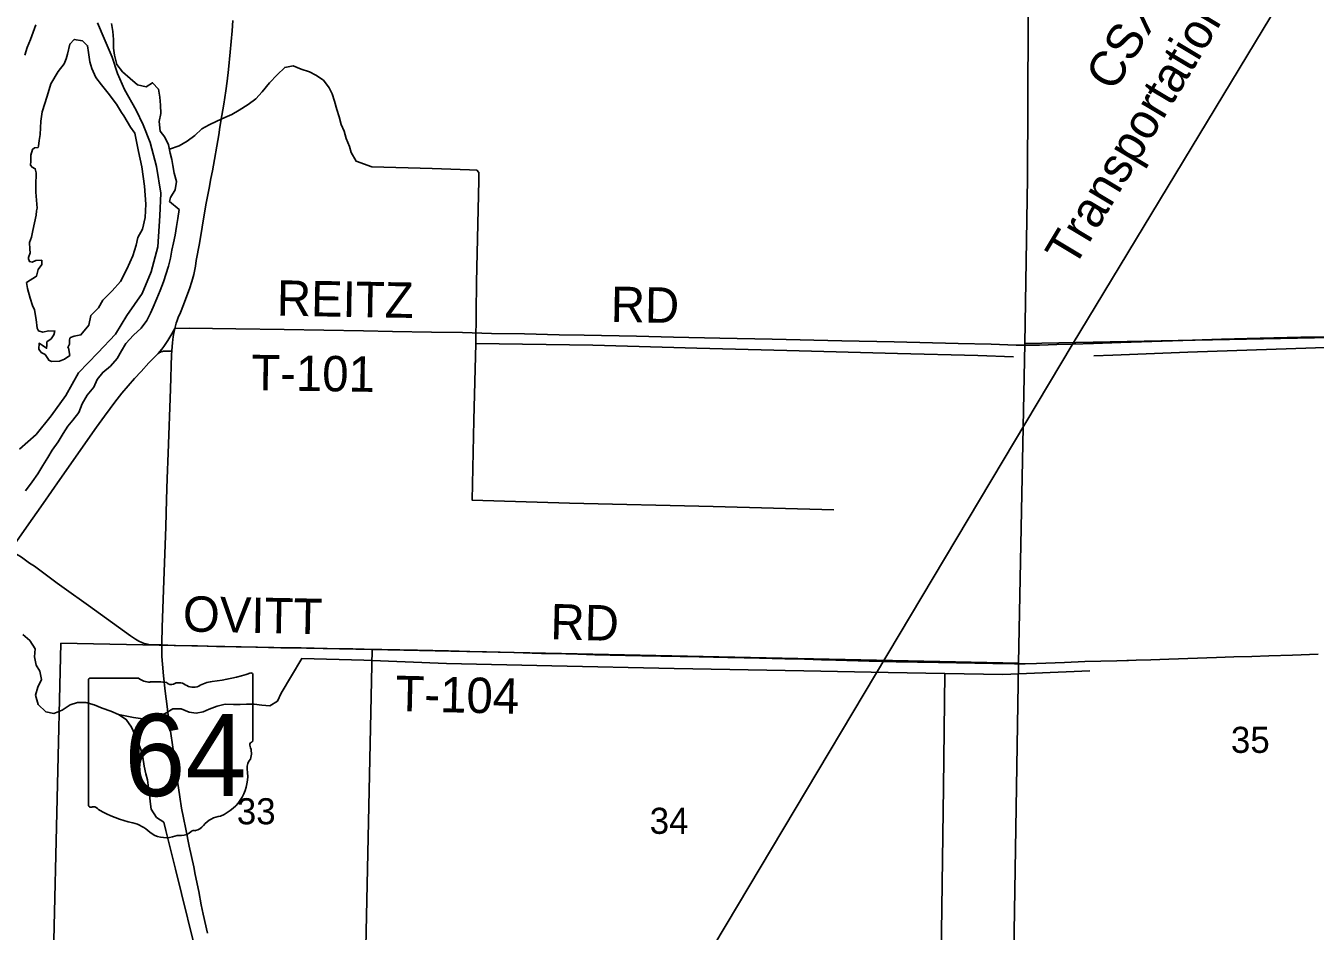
# Model space of a CAD drawing. Extents: x 1443599 to 1910620, y 1028088 to 1361369.
# Drawn here: x 1635252 to 1646176, y 1269443 to 1277115 of the extents above; entities that cross this region are included whole.
import ezdxf

# ---------------------------------------------------------------- set-up
doc = ezdxf.new("R2010")
doc.units = 0
for name, color, linetype in [('GM_X_Adjacent_County', 7, 'Continuous'), ('GM_X_Corporation', 7, 'Continuous'), ('GM_X_County', 7, 'Continuous'), ('GM_X_Interchange_Ramps', 7, 'Continuous'), ('GM_X_Major_River', 7, 'Continuous'), ('GM_X_Minor_River', 7, 'Continuous'), ('GM_X_Rail_Line', 7, 'Continuous'), ('GM_X_Rail_Line_Text', 7, 'Continuous'), ('GM_X_Section', 7, 'Continuous'), ('GM_X_Section_Text', 7, 'Continuous'), ('GM_X_State_Location', 7, 'Continuous'), ('GM_X_State_Route', 7, 'Continuous'), ('GM_X_State_Shield', 7, 'Continuous'), ('GM_X_Township', 7, 'Continuous'), ('GM_X_Township_Road', 7, 'Continuous'), ('GM_X_Township_Road_Text', 7, 'Continuous')]:
    doc.layers.add(name, color=color, linetype=linetype)

msp = doc.modelspace()

# ---------------------------------------------------------------- linework, layer by layer
at = {"layer": 'GM_X_Adjacent_County'}
msp.add_lwpolyline([(1635861, 1277141), (1635917, 1277006), (1635983, 1276848), (1636030, 1276711), (1636088, 1276575), (1636186, 1276399), (1636248, 1276276), (1636305, 1276126), (1636360, 1275922), (1636396, 1275697), (1636387, 1275504), (1636370, 1275242), (1636315, 1275030), (1636237, 1274848), (1636108, 1274660), (1636011, 1274501), (1635862, 1274343), (1635698, 1274173), (1635591, 1273982), (1635466, 1273811), (1635341, 1273653), (1635200, 1273527)], dxfattribs=at)
at = {"layer": 'GM_X_Corporation'}
msp.add_lwpolyline([(1635861, 1277141), (1635917, 1277006), (1635983, 1276848), (1636030, 1276711), (1636088, 1276575), (1636186, 1276399), (1636248, 1276276), (1636305, 1276126), (1636360, 1275922), (1636396, 1275697), (1636387, 1275504), (1636370, 1275242), (1636315, 1275030), (1636237, 1274848), (1636108, 1274660), (1636011, 1274501), (1635862, 1274343), (1635698, 1274173), (1635591, 1273982), (1635466, 1273811), (1635341, 1273653), (1635200, 1273527)], dxfattribs=at)
at = {"layer": 'GM_X_County'}
msp.add_lwpolyline([(1635200, 1273527), (1635341, 1273653), (1635466, 1273811), (1635591, 1273982), (1635698, 1274173), (1635862, 1274343), (1636011, 1274501), (1636108, 1274660), (1636237, 1274848), (1636315, 1275030), (1636370, 1275242), (1636387, 1275504), (1636396, 1275697), (1636360, 1275922), (1636305, 1276126), (1636248, 1276276), (1636186, 1276399), (1636088, 1276575), (1636030, 1276711), (1635983, 1276848), (1635917, 1277006), (1635861, 1277141)], dxfattribs=at)
at = {"layer": 'GM_X_Interchange_Ramps'}
msp.add_lwpolyline([(1636515, 1274551), (1636503, 1274529), (1636489, 1274505), (1636455, 1274448), (1636422, 1274398), (1636404, 1274375), (1636373, 1274339)], dxfattribs=at)
at = {"layer": 'GM_X_Major_River'}
msp.add_line((1636063, 1276379), (1636022, 1276451), dxfattribs=at)
for points in [[(1635337, 1277123), (1635292, 1276998), (1635265, 1276932), (1635243, 1276865)], [(1635250, 1273175), (1635306, 1273250), (1635353, 1273318), (1635396, 1273389), (1635440, 1273457), (1635477, 1273520), (1635526, 1273591), (1635570, 1273659), (1635609, 1273722), (1635650, 1273774), (1635701, 1273837), (1635731, 1273911), (1635772, 1273986), (1635828, 1274053), (1635857, 1274117), (1635904, 1274178), (1635969, 1274231), (1636025, 1274297), (1636064, 1274362), (1636101, 1274424), (1636165, 1274493), (1636230, 1274554), (1636277, 1274617), (1636308, 1274679), (1636331, 1274732), (1636363, 1274804), (1636392, 1274872), (1636419, 1274946), (1636462, 1275079), (1636478, 1275145), (1636489, 1275213), (1636504, 1275277), (1636517, 1275341), (1636529, 1275415), (1636540, 1275483), (1636551, 1275557), (1636469, 1275627), (1636479, 1275661), (1636517, 1275724), (1636528, 1275796), (1636509, 1275865), (1636498, 1275931), (1636489, 1275982), (1636476, 1276036), (1636460, 1276105), (1636429, 1276172), (1636390, 1276223), (1636383, 1276303), (1636397, 1276371), (1636394, 1276443), (1636389, 1276509), (1636377, 1276578), (1636326, 1276633), (1636271, 1276598), (1636199, 1276615), (1636136, 1276669), (1636071, 1276726), (1636024, 1276787), (1636003, 1276865), (1635995, 1276926), (1635994, 1276999), (1635991, 1277067), (1635979, 1277135)], [(1636022, 1276451), (1635950, 1276543), (1635894, 1276616), (1635845, 1276678), (1635813, 1276753), (1635796, 1276809), (1635784, 1276890), (1635776, 1276946), (1635733, 1276987), (1635663, 1276999), (1635624, 1276960), (1635606, 1276876), (1635595, 1276834), (1635578, 1276794), (1635526, 1276729), (1635465, 1276624), (1635433, 1276519), (1635392, 1276387), (1635380, 1276307), (1635373, 1276195), (1635366, 1276143), (1635359, 1276095), (1635356, 1276085), (1635326, 1276082), (1635310, 1276068), (1635295, 1276020), (1635295, 1275968), (1635293, 1275934), (1635306, 1275916), (1635332, 1275903), (1635341, 1275869), (1635337, 1275762), (1635337, 1275706), (1635350, 1275571), (1635343, 1275547), (1635339, 1275509), (1635313, 1275380), (1635300, 1275324), (1635283, 1275278), (1635286, 1275222), (1635289, 1275191), (1635276, 1275152), (1635274, 1275140), (1635283, 1275117), (1635307, 1275113), (1635337, 1275126), (1635387, 1275129), (1635387, 1275093), (1635358, 1275049), (1635342, 1274993), (1635259, 1274939), (1635266, 1274889), (1635290, 1274806), (1635310, 1274745), (1635327, 1274707), (1635339, 1274626), (1635348, 1274552), (1635359, 1274531), (1635397, 1274520), (1635445, 1274531), (1635499, 1274528), (1635490, 1274496), (1635468, 1274463), (1635431, 1274437), (1635430, 1274407), (1635428, 1274383), (1635392, 1274410), (1635365, 1274425), (1635363, 1274375), (1635383, 1274348), (1635416, 1274329), (1635438, 1274297), (1635447, 1274282), (1635471, 1274270), (1635537, 1274274), (1635580, 1274289), (1635625, 1274322), (1635614, 1274387), (1635608, 1274389), (1635623, 1274417), (1635622, 1274451), (1635624, 1274469), (1635632, 1274475), (1635661, 1274486), (1635719, 1274495), (1635785, 1274579), (1635803, 1274659), (1635867, 1274724), (1635904, 1274791), (1635984, 1274868), (1636056, 1274948), (1636107, 1275052), (1636160, 1275167), (1636186, 1275256), (1636201, 1275322), (1636241, 1275392), (1636264, 1275491), (1636270, 1275604), (1636258, 1275755), (1636236, 1275920), (1636207, 1276051)], [(1636207, 1276051), (1636180, 1276192), (1636177, 1276204), (1636140, 1276257), (1636082, 1276353), (1636063, 1276379)]]:
    msp.add_lwpolyline(points, dxfattribs=at)
at = {"layer": 'GM_X_Minor_River'}
for points in [[(1636469, 1276069), (1636552, 1276099), (1636619, 1276138), (1636684, 1276185), (1636745, 1276242), (1636806, 1276275), (1636872, 1276308), (1636939, 1276337), (1636998, 1276364), (1637060, 1276401), (1637137, 1276449), (1637200, 1276496), (1637256, 1276555), (1637317, 1276631), (1637381, 1276700), (1637446, 1276763), (1637518, 1276777), (1637584, 1276748), (1637657, 1276725), (1637709, 1276697), (1637774, 1276654), (1637823, 1276589), (1637848, 1276538), (1637867, 1276476), (1637886, 1276407), (1637907, 1276345), (1637925, 1276280), (1637950, 1276221), (1637967, 1276161), (1637996, 1276092), (1638008, 1276040), (1638050, 1275969), (1638183, 1275920)], [(1638183, 1275920), (1638694, 1275906), (1639012, 1275894), (1639074, 1275891), (1639089, 1275873), (1639090, 1275803), (1639070, 1274942), (1639066, 1274424), (1639048, 1273774), (1639033, 1273096), (1639859, 1273071), (1641075, 1273042), (1642098, 1273013)], [(1639066, 1274424), (1640057, 1274408), (1640936, 1274383), (1641701, 1274365), (1642638, 1274337), (1643319, 1274322), (1643621, 1274310)], [(1651013, 1274340), (1650437, 1274367), (1650164, 1274378), (1649493, 1274389), (1648753, 1274410), (1648132, 1274410), (1647364, 1274396), (1646689, 1274383), (1646262, 1274389), (1645679, 1274370), (1645098, 1274349), (1644462, 1274325), (1644300, 1274318)], [(1635227, 1271957), (1635286, 1271906), (1635331, 1271835), (1635325, 1271767), (1635340, 1271696), (1635371, 1271646), (1635384, 1271577), (1635353, 1271512), (1635335, 1271442), (1635356, 1271365), (1635421, 1271302), (1635491, 1271288), (1635561, 1271315), (1635628, 1271362), (1635691, 1271381), (1635761, 1271381), (1635831, 1271360), (1635900, 1271333), (1635974, 1271307), (1636039, 1271280), (1636103, 1271237), (1636149, 1271173), (1636176, 1271111), (1636205, 1271042), (1636226, 1270983), (1636243, 1270919), (1636255, 1270842), (1636270, 1270776), (1636283, 1270725), (1636292, 1270659), (1636301, 1270607), (1636306, 1270542), (1636314, 1270476), (1636361, 1270407), (1636423, 1270366), (1636439, 1270297)], [(1637415, 1271461), (1637591, 1271755), (1638117, 1271741), (1638816, 1271712), (1639709, 1271693), (1640744, 1271669), (1641845, 1271649), (1642558, 1271635), (1643037, 1271626), (1643529, 1271619), (1644267, 1271649)], [(1643037, 1271626), (1643026, 1270663), (1643011, 1269435), (1643004, 1268733)], [(1636039, 1271280), (1636165, 1271254), (1636245, 1271242), (1636303, 1271245), (1636367, 1271248), (1636434, 1271287), (1636497, 1271326), (1636569, 1271328), (1636635, 1271299), (1636695, 1271290), (1636755, 1271303), (1636807, 1271324), (1636874, 1271349), (1636942, 1271367), (1637012, 1271364), (1637067, 1271363), (1637121, 1271366), (1637187, 1271367), (1637253, 1271358), (1637319, 1271354), (1637384, 1271393), (1637415, 1271461)], [(1637406, 1266337), (1637069, 1267686), (1636933, 1268239), (1636726, 1269132), (1636521, 1269970), (1636439, 1270297)]]:
    msp.add_lwpolyline(points, dxfattribs=at)
at = {"layer": 'GM_X_Rail_Line'}
msp.add_lwpolyline([(1628024, 1247385), (1629402, 1249688), (1632328, 1254610), (1636988, 1262473), (1640104, 1267683), (1644118, 1274411), (1645800, 1277195), (1647368, 1279858), (1650566, 1285234), (1651910, 1287492), (1654331, 1291581), (1655752, 1293976)], dxfattribs=at)
at = {"layer": 'GM_X_Section'}
for points in [[(1643796, 1279828), (1649080, 1279911), (1648950, 1276529), (1648915, 1274524), (1643716, 1274422), (1643740, 1275820), (1643745, 1277139), (1643771, 1278507)], [(1643716, 1274422), (1648915, 1274524), (1648809, 1269125), (1647557, 1269165), (1643620, 1269091), (1643662, 1271713), (1643687, 1273004)], [(1635549, 1271885), (1638187, 1271829), (1638130, 1269174), (1636978, 1269202), (1635486, 1269247), (1635517, 1270567)], [(1638187, 1271829), (1643662, 1271713), (1643620, 1269091), (1642299, 1269070), (1638130, 1269174)]]:
    msp.add_lwpolyline(points, close=True, dxfattribs=at)
at = {"layer": 'GM_X_State_Route'}
for points in [[(1636770, 1275546), (1636781, 1275611), (1636805, 1275740), (1636819, 1275821), (1636834, 1275885), (1636887, 1276192), (1636897, 1276257), (1636914, 1276354), (1636930, 1276451), (1636948, 1276565), (1636958, 1276646), (1636969, 1276744), (1636984, 1276891), (1637000, 1277071), (1637007, 1277161)], [(1636489, 1274358), (1636489, 1274363), (1636494, 1274428), (1636497, 1274458), (1636500, 1274479), (1636504, 1274498), (1636515, 1274551), (1636527, 1274594), (1636534, 1274617), (1636543, 1274642), (1636562, 1274687), (1636587, 1274751), (1636617, 1274826), (1636639, 1274885), (1636659, 1274947), (1636675, 1275007), (1636689, 1275078), (1636697, 1275125), (1636723, 1275271), (1636770, 1275546)], [(1635173, 1272746), (1635258, 1272866), (1635400, 1273068), (1635541, 1273270), (1635851, 1273714), (1635918, 1273807), (1635967, 1273873), (1636006, 1273925), (1636067, 1274002), (1636119, 1274065), (1636173, 1274127), (1636229, 1274187), (1636296, 1274258), (1636373, 1274339), (1636385, 1274346), (1636394, 1274350), (1636402, 1274354), (1636411, 1274356), (1636418, 1274358), (1636426, 1274359), (1636442, 1274359), (1636458, 1274359), (1636489, 1274358)], [(1636791, 1269426), (1636754, 1269586), (1636738, 1269666), (1636717, 1269779), (1636688, 1269924), (1636675, 1269988), (1636637, 1270164), (1636607, 1270309), (1636587, 1270405), (1636572, 1270486), (1636557, 1270583), (1636537, 1270713), (1636494, 1271022), (1636480, 1271119), (1636462, 1271249), (1636450, 1271347), (1636434, 1271477), (1636419, 1271608), (1636410, 1271706), (1636406, 1271771), (1636404, 1271837), (1636404, 1271869), (1636405, 1271887), (1636409, 1272018), (1636423, 1272411), (1636438, 1272870), (1636444, 1273100), (1636450, 1273280), (1636458, 1273494), (1636478, 1274035), (1636488, 1274331)], [(1636488, 1274331), (1636489, 1274358)]]:
    msp.add_lwpolyline(points, dxfattribs=at)
at = {"layer": 'GM_X_State_Shield'}
for p, q in [((1635784, 1271570), (1635784, 1270513)), ((1636206, 1271588), (1635798, 1271588)), ((1637176, 1271061), (1637176, 1271614)), ((1637176, 1271061), (1637176, 1271061))]:
    msp.add_line(p, q, dxfattribs=at)
for centre, radius, start, end in [((1635800, 1271572), 16.1, 98.1301, 188.1301), ((1636303, 1271710), 156, 231.6195, 271.1119), ((1636355, 1270995), 562, 80.4867, 94.9883), ((1636482, 1271577), 45.1, 219.7921, 297.1024), ((1636548, 1271455), 93.8, 54.4667, 119.1411), ((1636869, 1271265), 297, 97.3462, 120.7689), ((1636681, 1273028), 1476, 275.8445, 288.9065), ((1637161, 1271616), 15.5, 351.8621, 97.738), ((1636670, 1271623), 113, 233.8562, 294.8282), ((1637173, 1271021), 24, 107.944, 210.337), ((1637020, 1270951), 144, 340.033, 23.6496), ((1637160, 1271059), 16.6, 289.6038, 7.7341), ((1637232, 1270830), 105, 136.8065, 186.9296), ((1636763, 1270760), 369, 292.3089, 8.9858), ((1635800, 1270511), 16.3, 171.9584, 258.3066), ((1635803, 1270619), 124, 267.339, 280.6039), ((1635828, 1270452), 44.8, 29.7484, 93.2717), ((1636394, 1271401), 1066, 240.4129, 257.1985), ((1636076, 1270038), 334, 47.1842, 75.836), ((1636663, 1270411), 119, 282.8732, 323.2771), ((1636919, 1270216), 202, 94.4031, 142.5768), ((1636436, 1270447), 212, 230.7004, 286.2918), ((1636559, 1270081), 174, 85.6951, 111.2099), ((1636574, 1270368), 113, 268.777, 315.5493), ((1636676, 1270265), 31.8, 65.7517, 132.6484)]:
    msp.add_arc(centre, radius, start, end, dxfattribs=at)
at = {"layer": 'GM_X_Township'}
msp.add_lwpolyline([(1635200, 1273527), (1635341, 1273653), (1635466, 1273811), (1635591, 1273982), (1635698, 1274173), (1635862, 1274343), (1636011, 1274501), (1636108, 1274660), (1636237, 1274848), (1636315, 1275030), (1636370, 1275242), (1636387, 1275504), (1636396, 1275697), (1636360, 1275922), (1636305, 1276126), (1636248, 1276276), (1636186, 1276399), (1636088, 1276575), (1636030, 1276711), (1635983, 1276848), (1635917, 1277006), (1635861, 1277141)], dxfattribs=at)
at = {"layer": 'GM_X_Township_Road'}
for points in [[(1636515, 1274551), (1636637, 1274552), (1636834, 1274551), (1637031, 1274548), (1637441, 1274541), (1638114, 1274530), (1638360, 1274526), (1638688, 1274519), (1638951, 1274515), (1639197, 1274509), (1639476, 1274504), (1639771, 1274497), (1639984, 1274494), (1640427, 1274485), (1640739, 1274478), (1641133, 1274469), (1641576, 1274459), (1642167, 1274445), (1642610, 1274437), (1643151, 1274423), (1643430, 1274416), (1643643, 1274410), (1643742, 1274409), (1643840, 1274410), (1643988, 1274414), (1644119, 1274417), (1644299, 1274423), (1644529, 1274431), (1645054, 1274448), (1645382, 1274459), (1645710, 1274468), (1646054, 1274477), (1646300, 1274480)], [(1635119, 1272668), (1635168, 1272641), (1635207, 1272617), (1635226, 1272604), (1635285, 1272563), (1635325, 1272535), (1635427, 1272460), (1635472, 1272427), (1635519, 1272392), (1635578, 1272350), (1635783, 1272202), (1636039, 1272018), (1636140, 1271945), (1636182, 1271918), (1636210, 1271901), (1636234, 1271890), (1636256, 1271882), (1636273, 1271877), (1636296, 1271873), (1636322, 1271871), (1636404, 1271869), (1636404, 1271869)], [(1636404, 1271869), (1636509, 1271864), (1636706, 1271860), (1636867, 1271856), (1637202, 1271849), (1637412, 1271845), (1637586, 1271843), (1637806, 1271839), (1638022, 1271836), (1638118, 1271834), (1638570, 1271823), (1638833, 1271818), (1639013, 1271813), (1639155, 1271810), (1639388, 1271804), (1639621, 1271797), (1639726, 1271795), (1639929, 1271790), (1640073, 1271786), (1640333, 1271780), (1640471, 1271777), (1640956, 1271767), (1641078, 1271766), (1641199, 1271762), (1641337, 1271759), (1641468, 1271757), (1641682, 1271751), (1641849, 1271747), (1641993, 1271743), (1642115, 1271740), (1642397, 1271732), (1642509, 1271728), (1642627, 1271726), (1642985, 1271720), (1643444, 1271712), (1643628, 1271710), (1643720, 1271710), (1643815, 1271712), (1644052, 1271721), (1644225, 1271727), (1644495, 1271735), (1644580, 1271738), (1644593, 1271738), (1644658, 1271740), (1644783, 1271743), (1644937, 1271749), (1645341, 1271762), (1645488, 1271767), (1645639, 1271772), (1645784, 1271776), (1645984, 1271783), (1646200, 1271791)]]:
    msp.add_lwpolyline(points, dxfattribs=at)

# ---------------------------------------------------------------- texts
at = {"layer": 'GM_X_Rail_Line_Text'}
for s, rotation, p in [('Transportation, Inc.', 59.0588, (1644131, 1275053)), ('CSX', 58.8094, (1644471, 1276547))]:
    msp.add_text(s, height=299, rotation=rotation, dxfattribs=at).set_placement(p)
at = {"layer": 'GM_X_Section_Text'}
for s, p in [('35', (1645462, 1270954)), ('33', (1637040, 1270349)), ('34', (1640538, 1270268))]:
    msp.add_text(s, height=221, rotation=0, dxfattribs=at).set_placement(p)
at = {"layer": 'GM_X_State_Location'}
msp.add_text('64', height=1, rotation=0, dxfattribs=at).set_placement((1636213, 1270898))
for s in ['s', 'r']:
    msp.add_text(s, height=1, dxfattribs=at).set_placement((1636465, 1270971))
at = {"layer": 'GM_X_State_Shield'}
msp.add_text('64', height=696.1, dxfattribs=at).set_placement((1636087, 1270588))
at = {"layer": 'GM_X_Township_Road_Text'}
for s, rotation, p in [('REITZ', 359.0289, (1637377, 1274659)), ('RD', 359.0128, (1640206, 1274606)), ('T-101', 359.1579, (1637160, 1274028)), ('OVITT', 358.8629, (1636581, 1271983)), ('RD', 358.5256, (1639694, 1271917)), ('T-104', 358.6037, (1638381, 1271309))]:
    msp.add_text(s, height=300, rotation=rotation, dxfattribs=at).set_placement(p)

doc.saveas('drawing.dxf')
